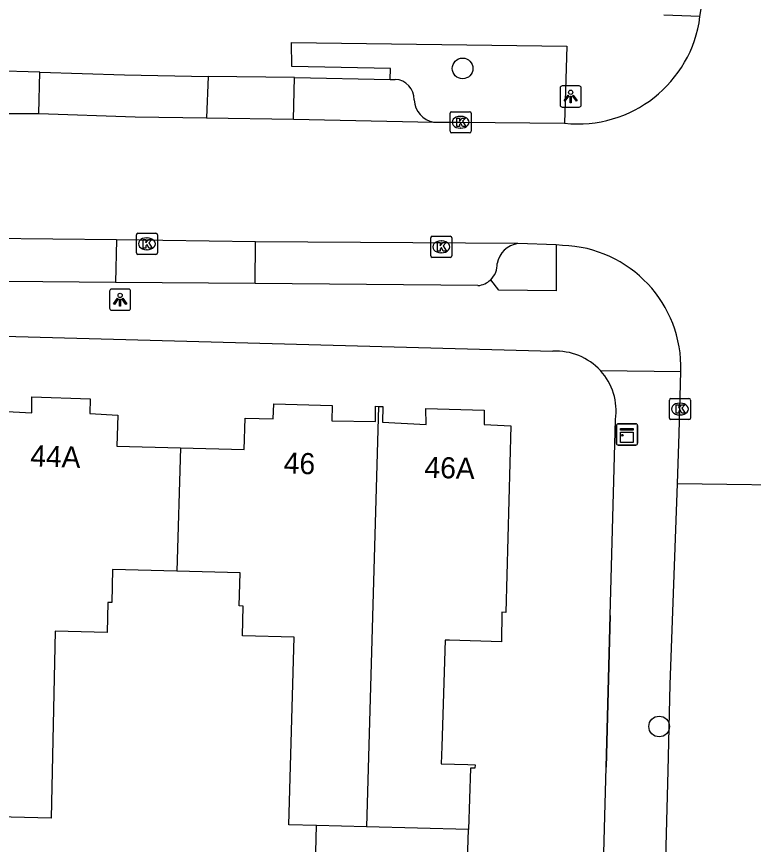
# Model space of a CAD drawing. Extents: x 162082 to 163393, y 388091 to 388632.
# Drawn here: x 162575.64 to 162610.54, y 388432.17 to 388471.39 of the extents above; entities that cross this region are included whole.
import ezdxf

# ---------------------------------------------------------------- set-up
doc = ezdxf.new("R2010")
doc.units = 0
for name, color, linetype in [('IMGEO_Boom', 7, 'Continuous'), ('IMGEO_Kast', 7, 'Continuous'), ('IMGEO_Kolk', 7, 'Continuous'), ('IMGEO_Lichtpunt', 7, 'Continuous'), ('IMGEO_Muur', 7, 'Continuous'), ('IMGEO_Pand', 7, 'Continuous'), ('IMGEO_Pand_nummerreeks', 7, 'Continuous'), ('IMGEO_Parkeervlak_open', 7, 'Continuous'), ('IMGEO_Rijbaan_lokaal_gesloten', 7, 'Continuous'), ('IMGEO_Rijbaan_lokaal_open', 7, 'Continuous'), ('IMGEO_Voetpad_open', 7, 'Continuous')]:
    doc.layers.add(name, color=color, linetype=linetype)

msp = doc.modelspace()

# ---------------------------------------------------------------- linework, layer by layer
at = {"layer": 'IMGEO_Boom'}
for centre in [(162596.765, 388468.93), (162606.072, 388437.755)]:
    msp.add_circle(centre, 0.489, dxfattribs=at)
at = {"layer": 'IMGEO_Kast'}
for p, q in [((162604.047, 388451.165), (162604.047, 388452.006)), ((162604.047, 388452.006), (162604.047, 388451.165)), ((162604.122, 388452.09), (162604.963, 388452.09)), ((162604.963, 388452.09), (162604.122, 388452.09)), ((162605.047, 388452.015), (162605.047, 388451.174)), ((162605.047, 388451.174), (162605.047, 388452.015)), ((162604.972, 388451.09), (162604.131, 388451.09)), ((162604.131, 388451.09), (162604.972, 388451.09))]:
    msp.add_line(p, q, dxfattribs=at)
for points in [[(162604.242, 388451.88), (162604.842, 388451.88), (162604.842, 388451.795), (162604.242, 388451.795), (162604.242, 388451.88)], [(162604.242, 388451.705), (162604.842, 388451.705), (162604.842, 388451.216), (162604.242, 388451.216), (162604.242, 388451.705)]]:
    msp.add_lwpolyline(points, dxfattribs=at)
msp.add_circle((162604.326, 388451.554), 0.0377, dxfattribs=at)
for centre, start, end in [((162604.125, 388452.012), 92.4484, 184.2845), ((162604.125, 388452.012), 92.4484, 184.2845), ((162604.969, 388452.012), 2.4484, 94.2845), ((162604.969, 388452.012), 2.4484, 94.2845), ((162604.125, 388451.168), 182.4484, 274.2845), ((162604.125, 388451.168), 182.4484, 274.2845), ((162604.969, 388451.168), 272.4484, 4.2845), ((162604.969, 388451.168), 272.4484, 4.2845)]:
    msp.add_arc(centre, 0.0779, start, end, dxfattribs=at)
at = {"layer": 'IMGEO_Kolk'}
for p, q in [((162596.169, 388465.955), (162596.169, 388466.807)), ((162596.244, 388466.881), (162597.096, 388466.881)), ((162597.17, 388466.807), (162597.17, 388465.955)), ((162596.657, 388466.661), (162596.682, 388466.661)), ((162596.68, 388466.101), (162596.655, 388466.101)), ((162597.096, 388465.881), (162596.244, 388465.881)), ((162581.315, 388460.197), (162581.315, 388461.049)), ((162581.39, 388461.123), (162582.242, 388461.123)), ((162581.803, 388460.903), (162581.828, 388460.903)), ((162582.316, 388461.049), (162582.316, 388460.197)), ((162595.255, 388460.051), (162595.255, 388460.903)), ((162595.33, 388460.977), (162596.182, 388460.977)), ((162596.256, 388460.903), (162596.256, 388460.051)), ((162595.743, 388460.757), (162595.768, 388460.757)), ((162582.242, 388460.123), (162581.39, 388460.123)), ((162581.826, 388460.343), (162581.801, 388460.343)), ((162595.766, 388460.197), (162595.741, 388460.197)), ((162596.182, 388459.977), (162595.33, 388459.977)), ((162606.555, 388452.368), (162606.555, 388453.22)), ((162606.63, 388453.294), (162607.482, 388453.294)), ((162607.043, 388453.074), (162607.068, 388453.074)), ((162607.556, 388453.22), (162607.556, 388452.368)), ((162607.482, 388452.294), (162606.63, 388452.294)), ((162607.066, 388452.514), (162607.041, 388452.514))]:
    msp.add_line(p, q, dxfattribs=at)
for points in [[(162596.169, 388465.955), (162596.169, 388466.807)], [(162596.244, 388466.881), (162597.096, 388466.881)], [(162597.17, 388466.807), (162597.17, 388465.955)], [(162596.49, 388466.581), (162596.613, 388466.581), (162596.613, 388466.43), (162596.743, 388466.581), (162596.907, 388466.581), (162596.761, 388466.43), (162596.914, 388466.181), (162596.762, 388466.181), (162596.677, 388466.345), (162596.613, 388466.278), (162596.613, 388466.181), (162596.49, 388466.181), (162596.49, 388466.581)], [(162597.096, 388465.881), (162596.244, 388465.881)], [(162581.315, 388460.197), (162581.315, 388461.049)], [(162581.39, 388461.123), (162582.242, 388461.123)], [(162582.316, 388461.049), (162582.316, 388460.197)], [(162595.255, 388460.051), (162595.255, 388460.903)], [(162595.33, 388460.977), (162596.182, 388460.977)], [(162596.256, 388460.903), (162596.256, 388460.051)], [(162581.636, 388460.823), (162581.759, 388460.823), (162581.759, 388460.672), (162581.889, 388460.823), (162582.053, 388460.823), (162581.907, 388460.672), (162582.06, 388460.423), (162581.908, 388460.423), (162581.823, 388460.587), (162581.759, 388460.52), (162581.759, 388460.423), (162581.636, 388460.423), (162581.636, 388460.823)], [(162595.576, 388460.677), (162595.699, 388460.677), (162595.699, 388460.526), (162595.829, 388460.677), (162595.993, 388460.677), (162595.847, 388460.526), (162596, 388460.277), (162595.848, 388460.277), (162595.763, 388460.441), (162595.699, 388460.374), (162595.699, 388460.277), (162595.576, 388460.277), (162595.576, 388460.677)], [(162582.242, 388460.123), (162581.39, 388460.123)], [(162596.182, 388459.977), (162595.33, 388459.977)], [(162606.555, 388452.368), (162606.555, 388453.22)], [(162606.63, 388453.294), (162607.482, 388453.294)], [(162607.556, 388453.22), (162607.556, 388452.368)], [(162606.876, 388452.994), (162606.999, 388452.994), (162606.999, 388452.843), (162607.129, 388452.994), (162607.293, 388452.994), (162607.147, 388452.843), (162607.3, 388452.594), (162607.148, 388452.594), (162607.063, 388452.758), (162606.999, 388452.691), (162606.999, 388452.594), (162606.876, 388452.594), (162606.876, 388452.994)], [(162607.482, 388452.294), (162606.63, 388452.294)]]:
    msp.add_lwpolyline(points, dxfattribs=at)
for centre, start, end in [((162596.246, 388466.805), 91.552, 178.448), ((162596.246, 388466.805), 91.552, 178.448), ((162597.094, 388466.805), 1.552, 88.448), ((162597.094, 388466.805), 1.552, 88.448), ((162596.246, 388465.957), 181.552, 268.448), ((162596.246, 388465.957), 181.552, 268.448), ((162597.094, 388465.957), 271.552, 358.448), ((162597.094, 388465.957), 271.552, 358.448), ((162581.392, 388461.047), 91.552, 178.448), ((162581.392, 388461.047), 91.552, 178.448), ((162582.24, 388461.047), 1.552, 88.448), ((162582.24, 388461.047), 1.552, 88.448), ((162595.332, 388460.901), 91.552, 178.448), ((162595.332, 388460.901), 91.552, 178.448), ((162596.18, 388460.901), 1.552, 88.448), ((162596.18, 388460.901), 1.552, 88.448), ((162581.392, 388460.199), 181.552, 268.448), ((162581.392, 388460.199), 181.552, 268.448), ((162582.24, 388460.199), 271.552, 358.448), ((162582.24, 388460.199), 271.552, 358.448), ((162595.332, 388460.053), 181.552, 268.448), ((162595.332, 388460.053), 181.552, 268.448), ((162596.18, 388460.053), 271.552, 358.448), ((162596.18, 388460.053), 271.552, 358.448), ((162606.632, 388453.218), 91.552, 178.448), ((162606.632, 388453.218), 91.552, 178.448), ((162607.48, 388453.218), 1.552, 88.448), ((162607.48, 388453.218), 1.552, 88.448), ((162606.632, 388452.37), 181.552, 268.448), ((162606.632, 388452.37), 181.552, 268.448), ((162607.48, 388452.37), 271.552, 358.448), ((162607.48, 388452.37), 271.552, 358.448)]:
    msp.add_arc(centre, 0.0765, start, end, dxfattribs=at)
for centre, major_axis, ratio, start_param, end_param in [((162596.656, 388466.381), (-0.387, 0.002), 0.722429, 4.712389, 7.853982), ((162596.681, 388466.381), (-0.39, 0.002), 0.717154, 1.570796, 4.712389), ((162581.802, 388460.623), (-0.387, 0.002), 0.722429, 4.712389, 7.853982), ((162581.827, 388460.623), (-0.39, 0.002), 0.717154, 1.570796, 4.712389), ((162595.742, 388460.477), (-0.387, 0.002), 0.722429, 4.712389, 7.853982), ((162595.767, 388460.477), (-0.39, 0.002), 0.717154, 1.570796, 4.712389), ((162607.042, 388452.794), (-0.387, 0.002), 0.722429, 4.712389, 7.853982), ((162607.067, 388452.794), (-0.39, 0.002), 0.717154, 1.570796, 4.712389)]:
    msp.add_ellipse(centre, major_axis=major_axis, ratio=ratio, start_param=start_param, end_param=end_param, dxfattribs=at)
at = {"layer": 'IMGEO_Lichtpunt'}
for p, q in [((162601.383, 388468.004), (162601.383, 388467.197)), ((162601.383, 388468.004), (162601.383, 388467.197)), ((162602.285, 388468.099), (162601.477, 388468.099)), ((162602.285, 388468.099), (162601.477, 388468.099)), ((162602.379, 388467.197), (162602.379, 388468.004)), ((162602.379, 388467.197), (162602.379, 388468.004)), ((162601.477, 388467.103), (162602.285, 388467.103)), ((162601.477, 388467.103), (162602.285, 388467.103)), ((162580.048, 388458.38), (162580.048, 388457.573)), ((162580.048, 388458.38), (162580.048, 388457.573)), ((162580.95, 388458.475), (162580.142, 388458.475)), ((162580.95, 388458.475), (162580.142, 388458.475)), ((162581.044, 388457.573), (162581.044, 388458.38)), ((162581.044, 388457.573), (162581.044, 388458.38)), ((162580.142, 388457.479), (162580.95, 388457.479)), ((162580.142, 388457.479), (162580.95, 388457.479))]:
    msp.add_line(p, q, dxfattribs=at)
for points in [[(162601.757, 388467.668), (162601.796, 388467.64), (162601.608, 388467.378), (162601.57, 388467.405), (162601.757, 388467.668)], [(162601.859, 388467.62), (162601.906, 388467.62), (162601.906, 388467.298), (162601.859, 388467.298), (162601.859, 388467.62)], [(162601.969, 388467.64), (162602.007, 388467.667), (162602.194, 388467.405), (162602.155, 388467.377), (162601.969, 388467.64)], [(162580.422, 388458.044), (162580.461, 388458.016), (162580.273, 388457.754), (162580.235, 388457.781), (162580.422, 388458.044)], [(162580.524, 388457.996), (162580.571, 388457.996), (162580.571, 388457.674), (162580.524, 388457.674), (162580.524, 388457.996)], [(162580.634, 388458.016), (162580.672, 388458.043), (162580.859, 388457.781), (162580.82, 388457.753), (162580.634, 388458.016)]]:
    msp.add_lwpolyline(points, dxfattribs=at)
for centre in [(162601.882, 388467.802), (162580.547, 388458.178)]:
    msp.add_circle(centre, 0.0994, dxfattribs=at)
for centre, start, end in [((162601.477, 388468.004), 90, 180), ((162601.477, 388468.004), 90, 180), ((162602.285, 388468.004), 0, 90), ((162602.285, 388468.004), 0, 90), ((162601.477, 388467.197), 180, 270), ((162601.477, 388467.197), 180, 270), ((162602.285, 388467.197), 270, 0), ((162602.285, 388467.197), 270, 360), ((162580.142, 388458.38), 90, 180), ((162580.142, 388458.38), 90, 180), ((162580.95, 388458.38), 0, 90), ((162580.95, 388458.38), 0, 90), ((162580.142, 388457.573), 180, 270), ((162580.142, 388457.573), 180, 270), ((162580.95, 388457.573), 270, 0), ((162580.95, 388457.573), 270, 360)]:
    msp.add_arc(centre, 0.0946, start, end, dxfattribs=at)
at = {"layer": 'IMGEO_Muur'}
msp.add_lwpolyline([(162603.756, 388443.021), (162603.561, 388435.824)], dxfattribs=at)
at = {"layer": 'IMGEO_Pand'}
for points in [[(162574.136, 388453.461), (162574.317, 388453.455), (162574.299, 388452.722), (162576.371, 388452.607), (162576.368, 388453.367), (162579.126, 388453.272), (162579.114, 388452.579), (162580.435, 388452.512), (162580.391, 388451.033), (162583.409, 388450.957)], [(162583.409, 388450.957), (162586.425, 388450.881), (162586.475, 388452.357), (162587.794, 388452.327), (162587.826, 388453.039), (162590.589, 388452.956), (162590.568, 388452.241), (162592.637, 388452.199), (162592.641, 388452.924), (162592.787, 388452.919)], [(162592.787, 388452.919), (162592.221, 388433.005)], [(162592.787, 388452.919), (162592.986, 388452.912), (162592.968, 388452.179), (162595.04, 388452.064), (162595.022, 388452.823), (162597.779, 388452.742), (162597.779, 388452.058), (162599.053, 388452.003), (162598.805, 388443.161), (162598.626, 388443.167), (162598.602, 388441.767), (162596.148, 388441.845), (162595.936, 388441.852), (162595.775, 388436.804), (162595.749, 388435.991), (162597.014, 388435.951), (162597.361, 388435.94), (162597.351, 388435.787), (162597.132, 388435.782), (162597.041, 388432.876)], [(162583.409, 388450.957), (162583.235, 388445.113)], [(162583.235, 388445.113), (162580.187, 388445.195), (162580.153, 388443.633), (162579.963, 388443.637), (162579.932, 388442.216), (162577.469, 388442.269), (162577.278, 388433.408), (162573.472, 388433.511)], [(162589.853, 388433.068), (162588.543, 388433.103), (162588.796, 388441.981), (162586.341, 388442.051), (162586.381, 388443.463), (162586.191, 388443.469), (162586.235, 388445.032), (162583.235, 388445.113)], [(162580.35, 388423.989), (162580.363, 388424.509), (162580.43, 388427.096), (162580.442, 388427.552), (162588.143, 388427.355), (162588.206, 388429.786), (162589.609, 388429.75), (162589.614, 388429.938), (162589.772, 388429.934), (162589.853, 388433.068)], [(162592.221, 388433.005), (162589.853, 388433.068)], [(162597.041, 388432.876), (162592.221, 388433.005)], [(162598.998, 388423.582), (162599, 388423.726), (162598.262, 388423.766), (162598.301, 388425.792), (162599.013, 388425.762), (162599.107, 388428.521), (162598.393, 388428.574), (162598.43, 388429.889), (162596.948, 388429.933), (162597.041, 388432.876)]]:
    msp.add_lwpolyline(points, dxfattribs=at)
at = {"layer": 'IMGEO_Parkeervlak_open'}
msp.add_lwpolyline([(162593.327, 388468.413), (162593.567, 388468.412)], dxfattribs=at)
for centre, radius, start, end in [((162593.513, 388467.45), 0.964, 359.2353, 86.8148), ((162595.571, 388467.47), 1.095, 181.7467, 260.6794), ((162599.549, 388459.483), 1.166, 98.0635, 169.741), ((162597.396, 388459.643), 1.006, 313.9247, 2.7539)]:
    msp.add_arc(centre, radius, start, end, dxfattribs=at)
at = {"layer": 'IMGEO_Rijbaan_lokaal_gesloten'}
for points in [[(162608.006, 388471.388), (162608.124, 388472.124), (162608.252, 388474.542)], [(162572.571, 388466.923), (162574.61, 388466.79), (162576.691, 388466.789)], [(162576.691, 388466.789), (162581.266, 388466.64), (162584.642, 388466.584)], [(162584.642, 388466.584), (162588.764, 388466.523)], [(162588.764, 388466.523), (162595.394, 388466.39)], [(162595.394, 388466.39), (162596.67, 388466.381), (162601.59, 388466.339)], [(162580.368, 388460.806), (162568.295, 388460.934)], [(162586.953, 388460.717), (162580.368, 388460.806)], [(162599.385, 388460.638), (162586.953, 388460.717)], [(162601.202, 388460.576), (162599.385, 388460.638)], [(162601.495, 388460.549), (162601.202, 388460.576)], [(162606.936, 388449.257), (162607.013, 388451.628), (162607.056, 388452.794), (162607.099, 388454.579)], [(162613.97, 388449.157), (162606.936, 388449.257)]]:
    msp.add_lwpolyline(points, dxfattribs=at)
for centre, radius, start, end in [((162602.223, 388472.135), 5.831, 263.7645, 352.6366), ((162601.31, 388454.76), 5.792, 358.2058, 88.1717)]:
    msp.add_arc(centre, radius, start, end, dxfattribs=at)
at = {"layer": 'IMGEO_Rijbaan_lokaal_open'}
for points in [[(162576.745, 388468.747), (162574.537, 388468.822), (162572.688, 388468.882)], [(162576.691, 388466.789), (162576.745, 388468.747)], [(162584.72, 388468.548), (162584.642, 388466.584)], [(162588.805, 388468.506), (162584.72, 388468.548)], [(162588.764, 388466.523), (162588.805, 388468.506)], [(162580.368, 388460.806), (162580.325, 388458.784)], [(162586.935, 388458.747), (162586.953, 388460.717)], [(162586.935, 388458.747), (162580.325, 388458.784)], [(162604.81, 388375.778), (162604.951, 388379.009), (162605.357, 388390.813), (162605.461, 388394.621), (162605.48, 388395.34), (162605.583, 388399.107), (162605.815, 388410.859), (162605.965, 388416.886), (162606.338, 388429.695), (162606.503, 388435.662), (162606.593, 388439.749), (162606.936, 388449.257)]]:
    msp.add_lwpolyline(points, dxfattribs=at)
at = {"layer": 'IMGEO_Voetpad_open'}
for points in [[(162608.006, 388471.388), (162606.293, 388471.459)], [(162593.327, 388468.413), (162593.349, 388468.925), (162588.677, 388469.028), (162588.662, 388470.165), (162601.696, 388469.978), (162601.59, 388466.339)], [(162576.745, 388468.747), (162580.757, 388468.629), (162584.72, 388468.548)], [(162588.805, 388468.506), (162593.327, 388468.413)], [(162601.202, 388460.576), (162601.202, 388458.395), (162598.484, 388458.425), (162598.094, 388458.918)], [(162580.325, 388458.784), (162568.266, 388458.901)], [(162597.488, 388458.641), (162586.935, 388458.747)], [(162547.269, 388457.001), (162601.04, 388455.529)], [(162603.293, 388454.618), (162607.099, 388454.579)], [(162601.897, 388374.162), (162603.561, 388435.824), (162603.756, 388443.021), (162604.006, 388452.295)]]:
    msp.add_lwpolyline(points, dxfattribs=at)
for centre, radius, start, end in [((162597.397, 388459.642), 1.005, 275.2086, 313.9212), ((162601.209, 388452.706), 2.828, 42.5366, 93.4316), ((162601.211, 388452.708), 2.825, 351.5948, 42.5309)]:
    msp.add_arc(centre, radius, start, end, dxfattribs=at)

# ---------------------------------------------------------------- texts
at = {"layer": 'IMGEO_Pand_nummerreeks'}
for s, rotation, p in [('44A', 358.0272, (162576.279, 388450.088)), ('46', 358.2794, (162588.282, 388449.744)), ('46A', 358.3155, (162594.949, 388449.544))]:
    msp.add_text(s, height=1, rotation=rotation, dxfattribs=at).set_placement(p)

doc.saveas('drawing.dxf')
